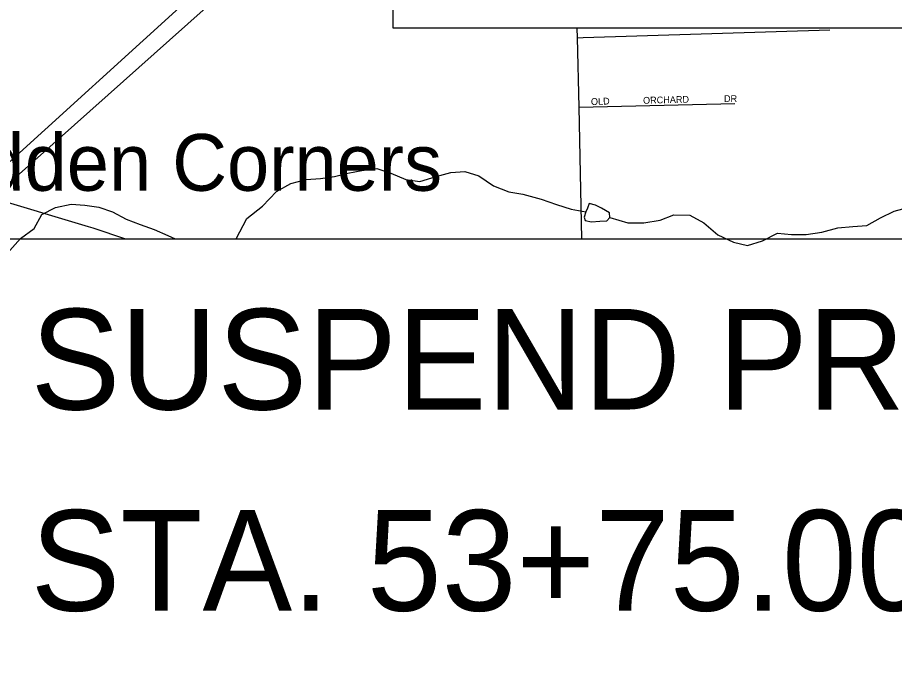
# Model space of a CAD drawing. Extents: x -37878.7 to -37844.7, y -19791.4 to -19769.4.
# Drawn here: x -37872.242 to -37871.021, y -19774.089 to -19773.183 of the extents above; entities that cross this region are included whole.
import ezdxf

# ---------------------------------------------------------------- set-up
doc = ezdxf.new("R2010")
doc.units = 0
for name, color, linetype in [('GM_X_Minor_Lake', 7, 'Continuous'), ('GM_X_Minor_River', 7, 'Continuous'), ('GM_X_State_Route', 7, 'Continuous'), ('GM_X_Township_Subdivision', 7, 'Continuous'), ('GM_X_Township_Subdivision_Text', 7, 'Continuous'), ('GM_X_Unincorporated_Text', 7, 'Continuous'), ('GM_X_US_Route', 7, 'Continuous'), ('TX_P_1', 7, 'Continuous')]:
    doc.layers.add(name, color=color, linetype=linetype)

msp = doc.modelspace()

# ---------------------------------------------------------------- linework, layer by layer
at = {"layer": 'GM_X_Minor_Lake'}
msp.add_line((-37871.4505, -19773.4532), (-37871.4529, -19773.4608), dxfattribs=at)
msp.add_lwpolyline([(-37871.4529, -19773.4608), (-37871.4518, -19773.4653), (-37871.4427, -19773.4669), (-37871.4313, -19773.4662), (-37871.4215, -19773.4655), (-37871.4173, -19773.4613), (-37871.4176, -19773.4548), (-37871.4289, -19773.4483), (-37871.4372, -19773.4441), (-37871.4459, -19773.4418), (-37871.4482, -19773.4482), (-37871.4505, -19773.4532)], dxfattribs=at)
at = {"layer": 'GM_X_Minor_River'}
for points in [[(-37871.9376, -19773.4907), (-37871.9227, -19773.4623), (-37871.901, -19773.4453), (-37871.8812, -19773.4249), (-37871.8615, -19773.4136), (-37871.8402, -19773.4084), (-37871.8202, -19773.4066), (-37871.8008, -19773.404), (-37871.7819, -19773.3992), (-37871.7625, -19773.3959), (-37871.7417, -19773.3929), (-37871.722, -19773.3995), (-37871.7013, -19773.4083), (-37871.6816, -19773.4111), (-37871.6592, -19773.4039), (-37871.6384, -19773.3987), (-37871.6191, -19773.3973), (-37871.5994, -19773.4031), (-37871.579, -19773.4169), (-37871.5579, -19773.4253), (-37871.5386, -19773.4284), (-37871.5129, -19773.4354), (-37871.4914, -19773.4431), (-37871.4713, -19773.4493), (-37871.4505, -19773.4532)], [(-37872.3552, -19773.5194), (-37872.3344, -19773.514), (-37872.3143, -19773.5151), (-37872.2948, -19773.5075), (-37872.2754, -19773.5132), (-37872.2561, -19773.5112), (-37872.2376, -19773.4903), (-37872.2185, -19773.4763), (-37872.208, -19773.4567), (-37872.1888, -19773.4472), (-37872.1673, -19773.4425), (-37872.148, -19773.444), (-37872.1286, -19773.4466), (-37872.1095, -19773.4531), (-37872.0904, -19773.4633), (-37872.0713, -19773.4708), (-37872.0518, -19773.4776), (-37872.0327, -19773.4863), (-37872.0224, -19773.4907)], [(-37871.4173, -19773.4613), (-37871.392, -19773.4686), (-37871.37, -19773.4684), (-37871.3473, -19773.4647), (-37871.3283, -19773.4572), (-37871.3059, -19773.458), (-37871.2863, -19773.4684), (-37871.2671, -19773.4852), (-37871.2452, -19773.4955), (-37871.2256, -19773.5002), (-37871.2047, -19773.4935), (-37871.1838, -19773.4829), (-37871.1641, -19773.4849), (-37871.1441, -19773.4846), (-37871.1221, -19773.4817), (-37871.0997, -19773.4757), (-37871.0789, -19773.4735), (-37871.0596, -19773.4721), (-37871.0406, -19773.4616), (-37871.0212, -19773.4522), (-37871.0022, -19773.4473)]]:
    msp.add_lwpolyline(points, dxfattribs=at)
at = {"layer": 'GM_X_State_Route'}
for points in [[(-37871.4582, -19773.3997), (-37871.46, -19773.3074), (-37871.4622, -19773.2109), (-37871.4626, -19773.1975)], [(-37871.4564, -19773.4907), (-37871.4582, -19773.3997)]]:
    msp.add_lwpolyline(points, dxfattribs=at)
at = {"layer": 'GM_X_Township_Subdivision'}
for points in [[(-37871.4622, -19773.2109), (-37871.4542, -19773.2104), (-37871.1111, -19773.1999)], [(-37871.46, -19773.3074), (-37871.2432, -19773.3026)]]:
    msp.add_lwpolyline(points, dxfattribs=at)
at = {"layer": 'GM_X_US_Route'}
msp.add_lwpolyline([(-37872.6324, -19773.372), (-37872.5213, -19773.385), (-37872.4135, -19773.4035), (-37872.2844, -19773.4312), (-37872.1434, -19773.4736), (-37872.1369, -19773.4756), (-37872.0917, -19773.4907)], dxfattribs=at)
at = {"layer": 'TX_P_1'}
for p, q in [((-37871.7188, -19773.1975), (-37871.7188, -19772.5985)), ((-37873.8226, -19774.8103), (-37871.7188, -19772.898)), ((-37869.74, -19773.1975), (-37871.7188, -19773.1975)), ((-37872.2676, -19773.4907), (-37870.2888, -19773.4907))]:
    msp.add_line(p, q, dxfattribs=at)
msp.add_lwpolyline([(-37871.7188, -19772.5985), (-37873.8226, -19774.8103), (-37871.7188, -19772.9363)], close=True, dxfattribs=at)

# ---------------------------------------------------------------- texts
at = {"layer": 'GM_X_Township_Subdivision_Text'}
for s, rotation, p in [('DR', 0, (-37871.2583, -19773.3004)), ('OLD', 1.9736, (-37871.4434, -19773.3046)), ('ORCHARD', 1.4694, (-37871.3709, -19773.3029))]:
    msp.add_text(s, height=0.00947, rotation=rotation, dxfattribs=at).set_placement(p)
at = {"layer": 'GM_X_Unincorporated_Text'}
msp.add_text('Madden Corners', height=0.078977, rotation=0, dxfattribs=at).set_placement((-37872.4375, -19773.4239))
at = {"layer": 'TX_P_1'}
for s, p in [('SUSPEND PROJECT', (-37872.2236, -19773.7283)), ('STA. 53+75.00', (-37872.2236, -19774.0083))]:
    msp.add_text(s, height=0.14, rotation=360, dxfattribs=at).set_placement(p)

doc.saveas('drawing.dxf')
